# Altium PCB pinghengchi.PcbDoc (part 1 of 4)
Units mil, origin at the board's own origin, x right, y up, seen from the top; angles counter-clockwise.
Board outline 3880 x 3935 mil, 2 copper layers (Top Layer, Bottom Layer); 79 components, 147 nets, 520 pads, 52 vias.
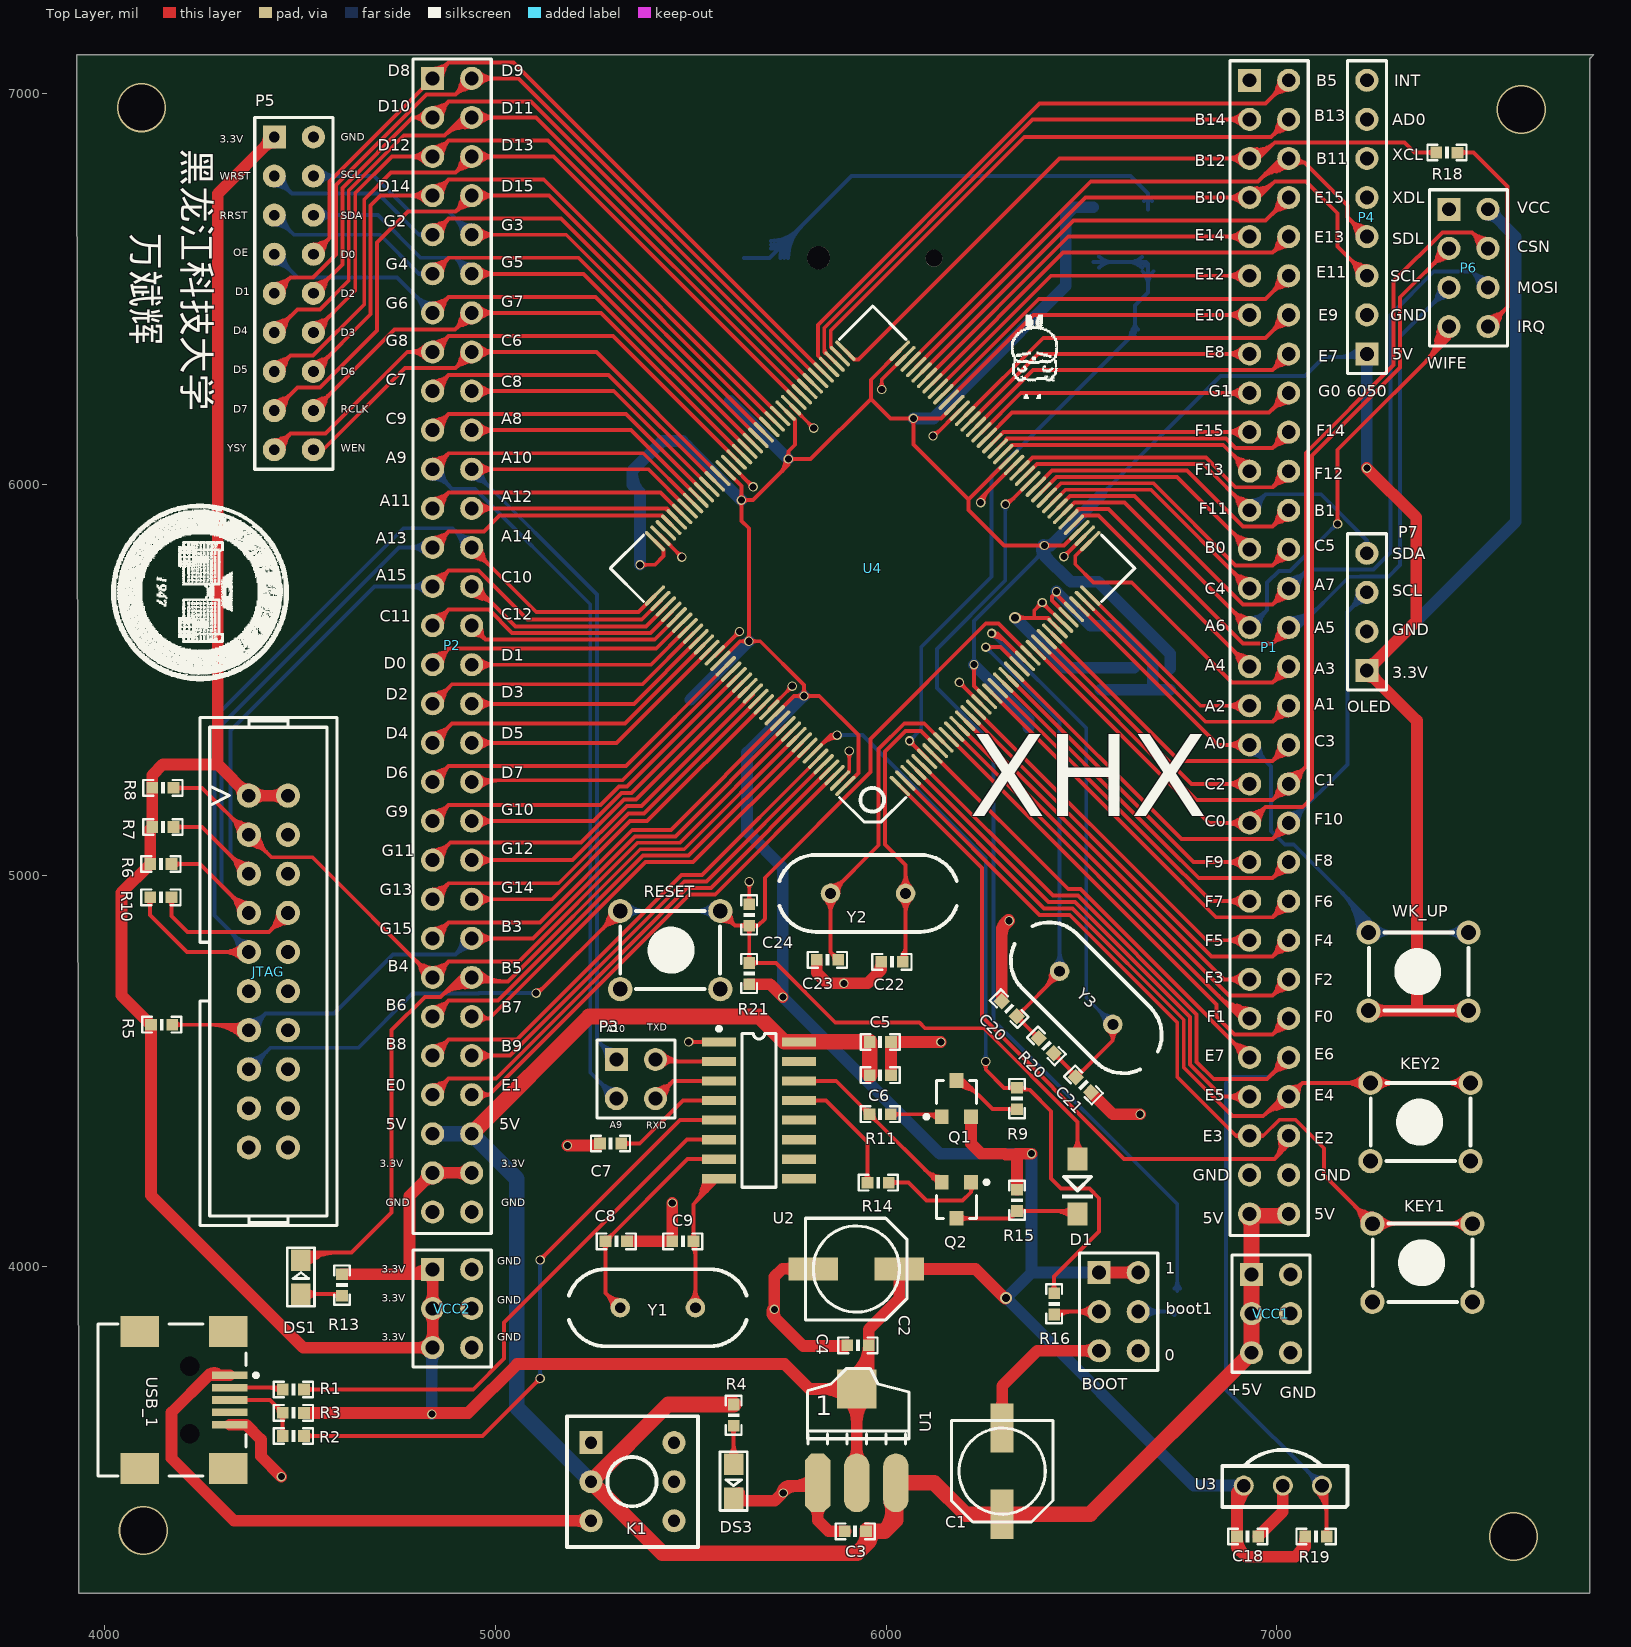
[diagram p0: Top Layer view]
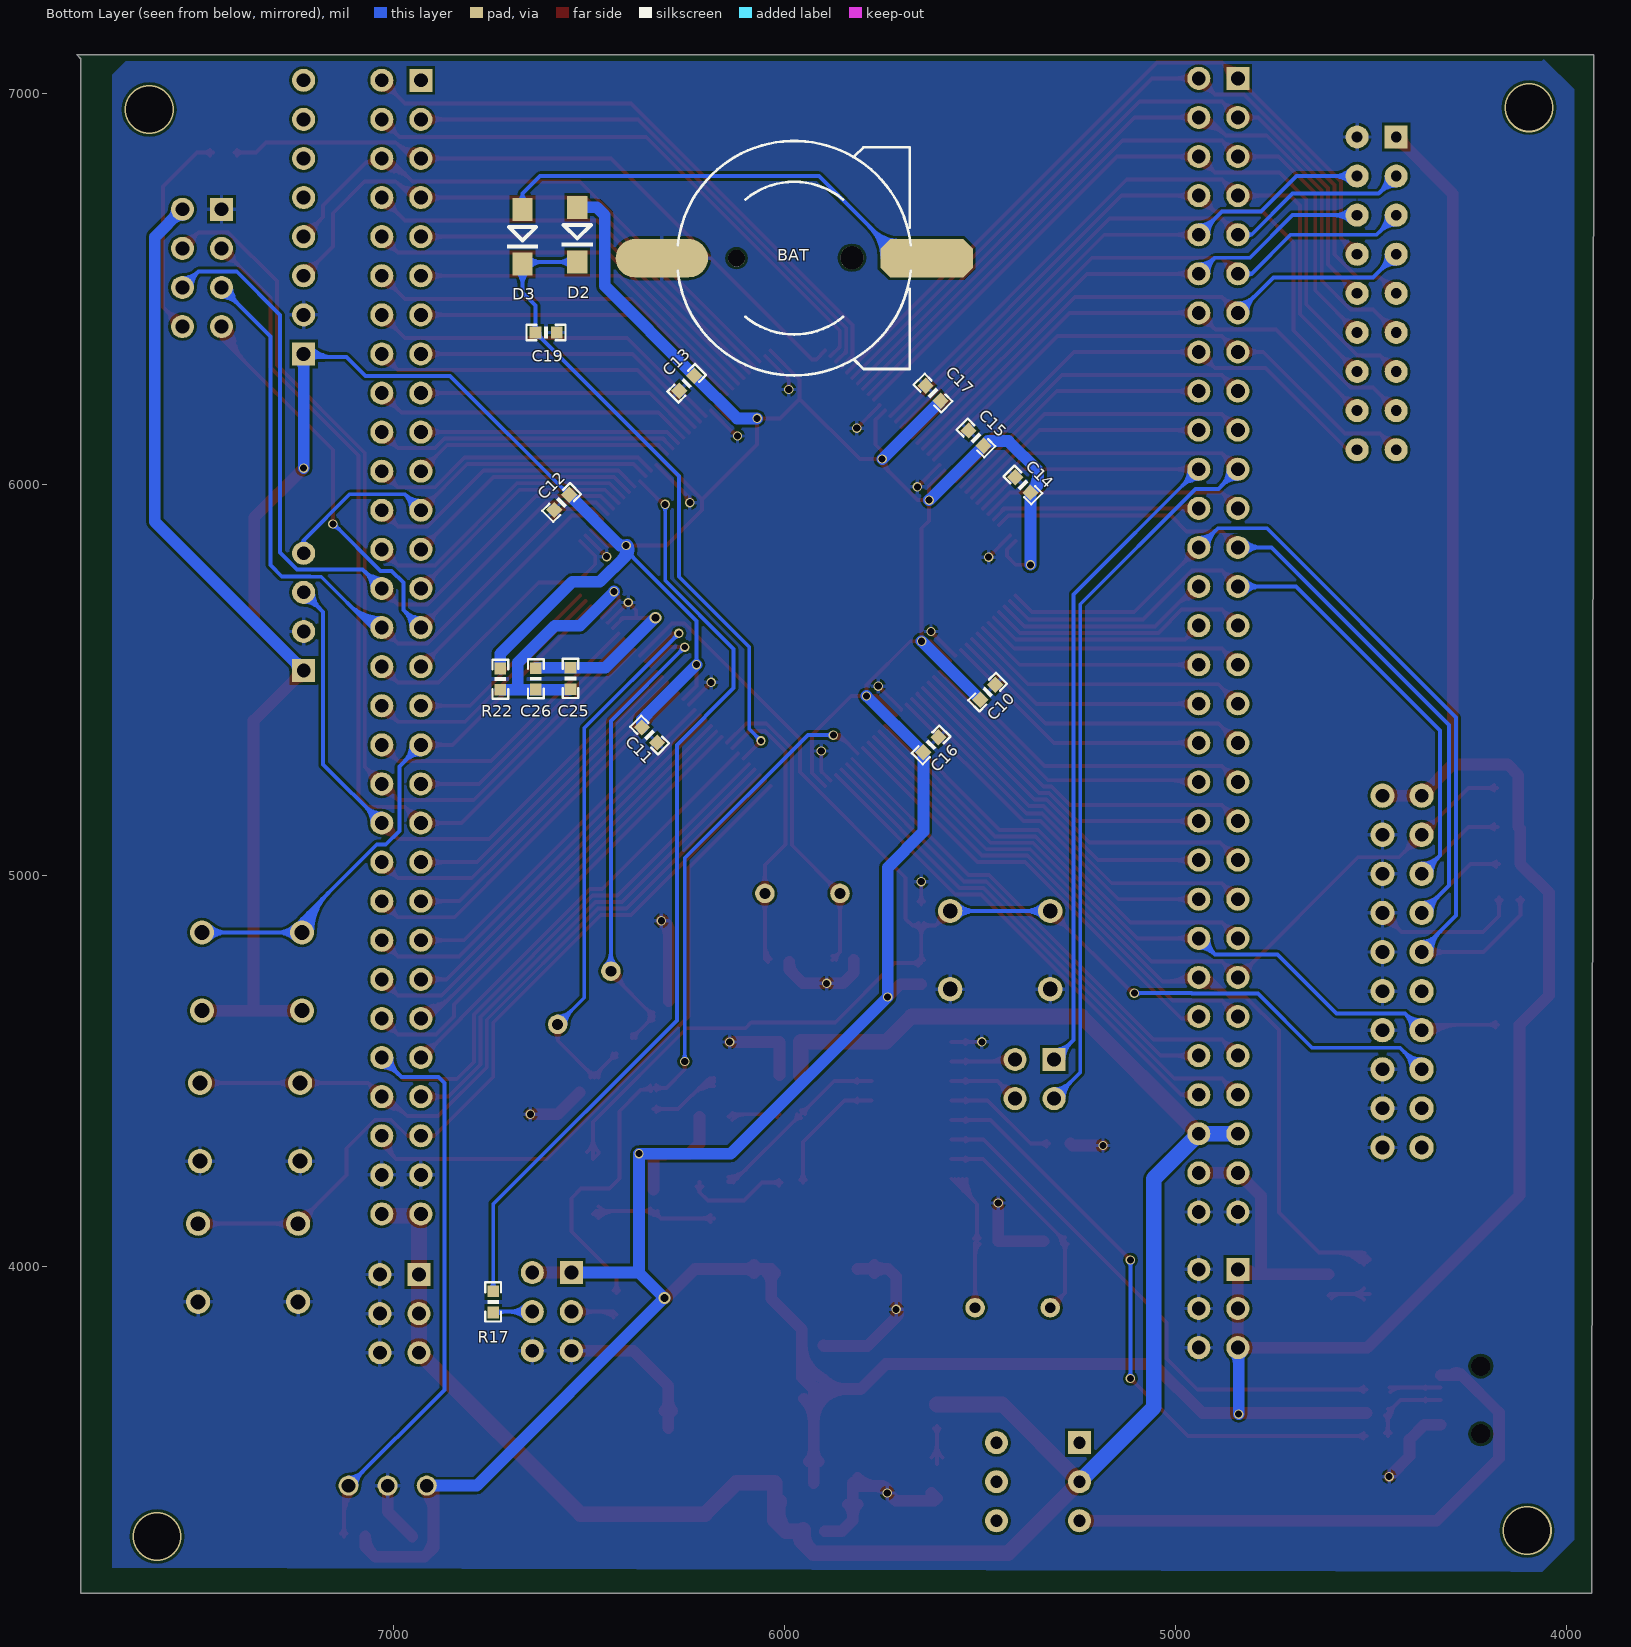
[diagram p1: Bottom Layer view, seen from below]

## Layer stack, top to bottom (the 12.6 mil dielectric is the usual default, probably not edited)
Top Layer: signal copper 1.4
Dielectric: dielectric 12.6, FR-4, Dk 4.8
Bottom Layer: signal copper 1.4

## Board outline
3930,7100 7810,7100 7800,7090 7800,3165 3935,3165 3935,3385

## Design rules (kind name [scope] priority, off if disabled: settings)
Clearance [All] p1: gap=6.5
HoleSize [All] p1: absolutevalues=TRUE maxlimit=120 minlimit=1 maxpercent=80.000 minpercent=20.000
HoleToHoleClearance [All] p1: gap=6 allowstackedmicrovias=TRUE
MinimumSolderMaskSliver [All] p1: minsoldermaskwidth=0
PolygonConnect [All] p1: connectstyle=Relief reliefconductorwidth=10 reliefentries=4 polygonreliefangle="90 Angle"
RoutingVias [All] p1: holewidth=16 width=24 viastyle="Through Hole" minholewidth=28 minwidth=50 maxholewidth=28 maxwidth=50
SilkToSilkClearance [All] p1: silktosilkclearance=1
SilkscreenOverComponentPads [All] p1: minsilkscreentomaskgap=0
SolderMaskExpansion [All] p1: expansion=2
Width [All] p1: maxlimit=80 minlimit=10 preferedwidth=10 minimp=50.000000 maximp=50.000000 favimp=50.000000
23 further rules are at their usual default settings.

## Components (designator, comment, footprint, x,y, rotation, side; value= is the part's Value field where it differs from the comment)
BAT "BATT" BATM 5975,6580 r90 bottom
BOOT "Header 3X2" HDR2X3 6545,3985 r270 top
C1 "47uf" CC6.56.5 6297,3477 r90 top
C2 "220UF" CC6.56.5 5924,3994 r180 top
C3 "100nf" 0603P 5921,3323 r0 top
C4 "100nf" 0603P 5928,3799 r0 top
C5 "100nf" 0603P 5985,4575 r0 top
C6 "10uf" 0603P 5985,4490 r0 top
C7 "104" 0603P 5295,4315 r0 top
C8 "22pf" 0603P 5310,4065 r180 top
C9 "22pf" 0603P 5480,4065 r0 top
C10 "100nf" 0603P 5480,5470 r315 bottom
C11 "100nf" 0603P 6345,5360 r45 bottom
C12 "100nf" 0603P 6570,5955 r135 bottom
C13 "100nf" 0603P 6250,6260 r135 bottom
C14 "100nf" 0603P 5390,6000 r225 bottom
C15 "100nf" 0603P 5510,6120 r225 bottom
C16 "100nf" 0603P 5625,5335 r315 bottom
C17 "100nf" 0603P 5620,6235 r225 bottom
C18 "100nf" 0603P 6925,3310 r180 top
C19 "100nf" 0603P 6610,6390 r180 bottom
C20 "20pf" 0603P 6315,4660 r315 top
C21 "20pf" 0603P 6505,4465 r135 top
C22 "10pf" 0603P 6015,4780 r0 top
C23 "10pf" 0603P 5850,4785 r0 top
C24 "100nf" 0603P 5650,4900 r270 top
C25 "10uf" 0603P 6547,5505 r270 bottom
C26 "100nf" 0603P 6636,5504 r270 bottom
D1 "1N4148" DIODE_SOP 6490,4275 r270 top
D2 "1N4148" DIODE_SOP 6530,6710 r270 bottom
D3 "1N4148" DIODE_SOP 6670,6705 r270 bottom
DS1 "LED1" SMDLED 4503,3930 r90 top
DS3 "LED1" SMDLED 5610,3495 r270 top
JTAG "JTAG" JTAG_20 4420,4755 r270 top
K1 "BUTTON" BTN8.5*8.5 5245,3550 r0 top
KEY1 "KEY_M" KEY_M 7500,3910 r180 top
KEY2 "KEY_M" KEY_M 7495,4270 r180 top
P1 "Header 30X2" HDR2X30#1 6930,7035 r270 top
P2 "Header 30X2" HDR2X30#2 4840,7040 r270 top
P3 "USART1" HDR2X2 5310,4530 r270 top
P4 "Header 8" HDR1X8 7230,6335 r90 top
P5 "OV7670" HDR2X9 4435,6890 r270 top
P6 "Header 4X2" HDR2X4 7440,6705 r270 top
P7 "Header 4" HDR1X4 7230,5525 r90 top
Q1 "S8550" SOT-23R 6180,4425 r0 top
Q2 "S8050" SOT-23R 6180,4175 r180 top
R1 "10K" 0603P 4484,3686 r180 top
R2 "10K" 0603P 4484,3567 r180 top
R3 "1.5K" 0603P 4484,3626 r180 top
R4 "2K" 0603P 5610,3620 r90 top
R5 "10K" 0603P 4147,4619 r180 top
R6 "10K" 0603P 4145,5030 r180 top
R7 "10K" 0603P 4150,5125 r180 top
R8 "10K" 0603P 4150,5225 r180 top
R9 "1K" 0603P 6335,4430 r90 top
R10 "10K" 0603P 4145,4945 r180 top
R11 "1K" 0603P 5985,4390 r180 top
R13 "600" 0603P 4608,3953 r90 top
R14 "1K" 0603P 5980,4215 r180 top
R15 "10K" 0603P 6335,4170 r270 top
R16 "100k" 0603P 6430,3905 r270 top
R17 "100k" 0603P 6745,3910 r90 bottom
R18 "1K" 0603P 7435,6850 r180 top
R19 "4.7K" 0603P 7100,3310 r180 top
R20 "1M" 0603P 6410,4565 r135 top
R21 "10K" 0603P 5650,4750 r270 top
R22 "10K" 0603P 6727,5503 r90 bottom
RESET "KEY_M" KEY_M 5320,4910 r0 top
U1 "AMS1117-3.3" AMS1117 5825,3447 r0 top
U2 "CH340G" SOP16M 5675,4400 r270 top
U3 "HS0038" HS0038 7115,3440 r180 top
U4 "STM32F103ZET6" LQFP144 6035,5230 r135 top
USB_1 "USB" USB/SM0.8-6H5 4012,3659 r180 top
VCC1 "Header 3X2" HDR2X3 6935,3980 r270 top
VCC2 "Header 3X2" HDR2X3 4840,3993 r270 top
WK_UP "KEY_M" KEY_M 7490,4655 r180 top
Y1 "12MHz" XTAL_US 5320,3895 r0 top
Y2 "32.768K" XTAL_US 6050,4955 r180 top
Y3 "8MHz" XTAL_US 6580,4620 r135 top

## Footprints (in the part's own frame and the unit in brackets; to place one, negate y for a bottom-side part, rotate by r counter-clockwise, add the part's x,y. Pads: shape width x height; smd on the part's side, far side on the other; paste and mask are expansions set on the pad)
0603P [mil]
  rect 30x30 smd: 1(-27,0) 2(27.5,-0.06)
  silkscreen extent -50,-20 50,20
AMS1117 [mil]
  oct 65x150 smd: 1(0.03,-0.06)
  oval 65x150 smd: 2(100.03,-0.06) 3(200.03,-0.06)
  rect 100x100 smd: 4(100.03,239.94)
  silkscreen extent -26,100 234,293
BATM [mm]
  round 1.1 hole 1.1 unplated: 0(0,3.748)
  round 1.5 hole 1.5 unplated: 0(0.025,-3.752)
  oct 2.5x6 smd: 1(0,-8.602)
  oval 2.5x6 smd: 2(0,8.598)
  silkscreen extent -7.62,-7.58 7.62,7.57
BTN8.5*8.5 [mm]
  rect 1.5x1.5 hole 0.8: 1(0,0)
  round 1.5 hole 0.8: 2(0,-2.54) 3(0,-5.08) 4(5.4,-5.08) 5(5.4,-2.54) 6(5.4,0)
  silkscreen extent -1.55,-6.79 6.95,1.71
CC6.56.5 [mm]
  rect 3.2x1.5 smd: 1(-2.794,0) 2(2.8,0)
  silkscreen extent -3.3,-3.3 3.3,3.3
DIODE_SOP [mm]
  rect 1.5x1.3 smd: 1(0,0) 2(3.556,0)
  silkscreen extent 1.14,-1.02 2.56,1.02
HDR1X4 [mm]
  rect 1.5x1.5 hole 0.889: 1(0,0)
  round 1.5 hole 0.889: 2(2.54,0) 3(5.08,0) 4(7.62,0)
  silkscreen extent -1.27,-1.27 8.89,1.27
HDR1X8 [mm] "Connector; Header; 8 Position"
  rect 1.5x1.5 hole 0.9: 1(0,0)
  round 1.5 hole 0.9: 2(2.54,0) 3(5.08,0) 4(7.62,0) 5(10.16,0) 6(12.7,0) 7(15.24,0) 8(17.78,0)
  silkscreen extent -1.27,-1.27 19.05,1.27
HDR2X2 [mm]
  rect 1.5x1.5 hole 0.9: 1(0,0)
  round 1.5 hole 0.9: 2(0,2.54) 3(2.54,0) 4(2.54,2.54)
  silkscreen extent -1.27,-1.27 3.81,3.81
HDR2X3 [mm]
  rect 1.5x1.5 hole 0.9: 1(0,0)
  round 1.5 hole 0.9: 2(0,2.54) 3(2.54,0) 4(2.54,2.54) 5(5.08,0) 6(5.08,2.54)
  silkscreen extent -1.27,-1.27 6.35,3.81
HDR2X4 [mm] "Connector; Header; 4x2 Position"
  rect 1.5x1.5 hole 0.9: 1(0,0)
  round 1.5 hole 0.9: 2(0,2.54) 3(2.54,0) 4(2.54,2.54) 5(5.08,0) 6(5.08,2.54) 7(7.62,0) 8(7.62,2.54)
  silkscreen extent -1.27,-1.27 8.89,3.81
HDR2X9 [mm]
  rect 1.5x1.5 hole 0.7: 1(0,0)
  round 1.5 hole 0.7: 2(0,2.54) 3(2.54,0) 4(2.54,2.54) 5(5.08,0) 6(5.08,2.54) 7(7.62,0) 8(7.62,2.54) 9(10.16,0) 10(10.16,2.54) 11(12.7,0) 12(12.7,2.54) 13(15.24,0) 14(15.24,2.54) 15(17.78,0) 16(17.78,2.54) 17(20.32,0) 18(20.32,2.54)
  silkscreen extent -1.27,-1.27 21.59,3.81
HDR2X30#1 [mm] "Connector; Header; 30x2 Position"
  rect 1.5x1.5 hole 0.9: 1(0,0)
  round 1.5 hole 0.9: 2(0,2.54) 3(2.54,0) 4(2.54,2.54) 5(5.08,0) 6(5.08,2.54) 7(7.62,0) 8(7.62,2.54) 9(10.16,0) 10(10.16,2.54) 11(12.7,0) 12(12.7,2.54) 13(15.24,0) 14(15.24,2.54) 15(17.78,0) 16(17.78,2.54) 17(20.32,0) 18(20.32,2.54) 19(22.86,0) 20(22.86,2.54) 21(25.4,0) 22(25.4,2.54) 23(27.94,0) 24(27.94,2.54) 25(30.48,0) 26(30.48,2.54) 27(33.02,0) 28(33.02,2.54) 29(35.56,0) 30(35.56,2.54) 31(38.1,0) 32(38.1,2.54) 33(40.64,0) 34(40.64,2.54) 35(43.18,0) 36(43.18,2.54) 37(45.72,0) 38(45.72,2.54) 39(48.26,0) 40(48.26,2.54) 41(50.8,0) 42(50.8,2.54) 43(53.34,0) 44(53.34,2.54) 45(55.88,0) 46(55.88,2.54) 47(58.42,0) 48(58.42,2.54) 49(60.96,0) 50(60.96,2.54) 51(63.5,0) 52(63.5,2.54) 53(66.04,0) 54(66.04,2.54) 55(68.58,0) 56(68.58,2.54) 57(71.12,0) 58(71.12,2.54) 59(73.66,0) 60(73.66,2.54)
  silkscreen extent -1.27,-1.27 75.06,3.81
HDR2X30#2 [mm] "Connector; Header; 30x2 Position"
  rect 1.5x1.5 hole 0.9: 1(0,0)
  round 1.5 hole 0.9: 2(0,2.54) 3(2.54,0) 4(2.54,2.54) 5(5.08,0) 6(5.08,2.54) 7(7.62,0) 8(7.62,2.54) 9(10.16,0) 10(10.16,2.54) 11(12.7,0) 12(12.7,2.54) 13(15.24,0) 14(15.24,2.54) 15(17.78,0) 16(17.78,2.54) 17(20.32,0) 18(20.32,2.54) 19(22.86,0) 20(22.86,2.54) 21(25.4,0) 22(25.4,2.54) 23(27.94,0) 24(27.94,2.54) 25(30.48,0) 26(30.48,2.54) 27(33.02,0) 28(33.02,2.54) 29(35.56,0) 30(35.56,2.54) 31(38.1,0) 32(38.1,2.54) 33(40.64,0) 34(40.64,2.54) 35(43.18,0) 36(43.18,2.54) 37(45.72,0) 38(45.72,2.54) 39(48.26,0) 40(48.26,2.54) 41(50.8,0) 42(50.8,2.54) 43(53.34,0) 44(53.34,2.54) 45(55.88,0) 46(55.88,2.54) 47(58.42,0) 48(58.42,2.54) 49(60.96,0) 50(60.96,2.54) 52(63.5,2.54) 53(66.04,0) 54(66.04,2.54) 55(68.58,0) 56(68.58,2.54) 57(71.12,0) 58(71.12,2.54) 59(73.66,0) 60(73.66,2.54)
  round 1.499 hole 0.9: 51(63.5,0)
  silkscreen extent -1.27,-1.27 75.06,3.81
HS0038 [mm]
  round 1.3 hole 0.889: 1(0,0) 2(2.54,0) 3(5.08,0)
  silkscreen extent -1.65,-2.32 6.48,1.4
JTAG_20 [mil]
  round 62 hole 35: 1(-450,-50) 2(-450,50) 3(-350,-50) 4(-350,50) 5(-250,-50) 6(-250,50) 7(-150,-50) 8(-150,50) 9(-50,-50) 10(-50,50) 11(50,-50) 12(50,50) 13(150,-50) 14(150,50) 15(250,-50) 16(250,50) 17(350,-50) 18(350,50) 19(450,-50) 20(450,50)
  silkscreen extent -650,-175 650,175
KEY_M [mil]
  round 62 hole 38: 1(0,0) 1(255.91,0) 2(0,-200) 2(255.91,-200)
  silkscreen extent 0,-200 255,0
LQFP144 [mil]
  oval 70x9.5 smd: 1(-0.36,0.02) 2(-0.35,-19.66) 3(-0.35,-39.35) 4(-0.35,-59.03) 5(-0.35,-78.72) 6(-0.35,-98.4) 7(-0.35,-118.09) 8(-0.35,-137.77) 9(-0.35,-157.46) 10(-0.35,-177.14) 11(-0.35,-196.83) 12(-0.36,-216.51) 13(-0.35,-236.2) 14(-0.35,-255.88) 15(-0.35,-275.57) 16(-0.35,-295.25) 17(-0.35,-314.94) 18(-0.35,-334.62) 19(-0.35,-354.31) 20(-0.35,-373.99) 21(-0.35,-393.68) 22(-0.35,-413.36) 23(-0.35,-433.05) 24(-0.35,-452.73) 25(-0.35,-472.42) 26(-0.35,-492.1) 27(-0.35,-511.79) 28(-0.36,-531.47) 29(-0.35,-551.16) 30(-0.35,-570.84) 31(-0.35,-590.53) 32(-0.35,-610.21) 33(-0.35,-629.9) 34(-0.35,-649.58) 35(-0.35,-669.27) 36(-0.35,-688.95) 73(885.47,-688.95) 74(885.47,-669.27) 75(885.47,-649.58) 76(885.47,-629.9) 77(885.47,-610.21) 78(885.47,-590.53) 79(885.47,-570.84) 80(885.47,-551.16) 81(885.47,-531.47) 82(885.47,-511.79) 83(885.47,-492.1) 84(885.47,-472.42) 85(885.47,-452.73) 86(885.47,-433.05) 87(885.47,-413.36) 88(885.47,-393.68) 89(885.47,-373.99) 90(885.47,-354.31) 91(885.47,-334.62) 92(885.47,-314.94) 93(885.47,-295.25) 94(885.47,-275.57) 95(885.47,-255.88) 96(885.47,-236.2) 97(885.47,-216.51) 98(885.47,-196.83) 99(885.47,-177.14) 100(885.47,-157.46) 101(885.47,-137.77) 102(885.47,-118.09) 103(885.47,-98.4) 104(885.47,-78.72) 105(885.47,-59.03) 106(885.47,-39.35) 107(885.47,-19.66) 108(885.47,0.02)
  oval 9.5x70 smd: 37(98.07,-787.38) 38(117.76,-787.38) 39(137.44,-787.38) 40(157.13,-787.38) 41(176.81,-787.38) 42(196.5,-787.38) 43(216.18,-787.38) 44(235.87,-787.38) 45(255.55,-787.38) 46(275.24,-787.38) 47(294.92,-787.38) 48(314.61,-787.38) 49(334.29,-787.38) 50(353.98,-787.38) 51(373.66,-787.38) 52(393.35,-787.38) 53(413.03,-787.38) 54(432.72,-787.38) 55(452.4,-787.38) 56(472.09,-787.38) 57(491.77,-787.38) 58(511.46,-787.38) 59(531.14,-787.38) 60(550.83,-787.38) 61(570.51,-787.38) 62(590.2,-787.38) 63(609.88,-787.38) 64(629.57,-787.38) 65(649.25,-787.38) 66(668.94,-787.38) 67(688.62,-787.38) 68(708.31,-787.38) 69(727.99,-787.38) 70(747.68,-787.38) 71(767.36,-787.38) 72(787.05,-787.38) 109(787.05,98.45) 110(767.36,98.45) 111(747.67,98.45) 112(727.99,98.45) 113(708.31,98.45) 114(688.62,98.45) 115(668.94,98.45) 116(649.25,98.45) 117(629.57,98.45) 118(609.88,98.45) 119(590.2,98.45) 120(570.51,98.45) 121(550.82,98.45) 122(531.14,98.45) 123(511.46,98.45) 124(491.77,98.45) 125(472.09,98.45) 126(452.4,98.45) 127(432.72,98.45) 128(413.03,98.45) 129(393.35,98.45) 130(373.66,98.45) 131(353.98,98.45) 132(334.29,98.45) 133(314.61,98.45) 134(294.92,98.45) 135(275.24,98.45) 136(255.55,98.45) 137(235.87,98.45) 138(216.18,98.45) 139(196.5,98.45) 140(176.81,98.45) 141(157.13,98.45) 142(137.44,98.45) 143(117.76,98.45) 144(98.07,98.45)
  silkscreen extent -32,-819 917,130
SMDLED [mm]
  rect 1.4x1.27 smd: 1(0.001,-0.002) 2(2.211,-0.002)
  silkscreen extent -0.8,-0.89 3.01,0.89
SOP16M [mm]
  rect 0.6x2.2 smd: 1(-4.445,-2.6) 2(-3.175,-2.6) 3(-1.905,-2.6) 4(-0.635,-2.6) 5(0.635,-2.6) 6(1.905,-2.6) 7(3.175,-2.6) 8(4.445,-2.6) 9(4.445,2.6) 10(3.175,2.6) 11(1.905,2.6) 12(0.635,2.6) 13(-0.635,2.6) 14(-1.905,2.6) 15(-3.175,2.6) 16(-4.445,2.6)
  silkscreen extent -5.42,-2.72 5,1.1
SOT-23R [mm]
  rect 0.9x0.95 smd: 1(0.95,-1.048) 2(-0.95,-1.048) 3(0,1.302)
  silkscreen extent -2.07,-1.17 1.3,1.3
USB/SM0.8-6H5 [mm]
  rect 2.3x0.5 smd: 1(-7.85,-1.6) 2(-7.85,-0.8) 3(-7.85,0) 4(-7.85,0.8) 5(-7.85,1.6)
  rect 2.5x2 smd: 6(-7.75,4.45) 7(-1.996,4.45) 8(-7.75,-4.45) 9(-1.996,-4.45)
  round 0.6 hole 1.27 unplated: MH1(-5.25,2.2) MH2(-5.25,-2.2)
  silkscreen extent -9.68,-4.95 0.7,4.95
XTAL_US [mil]
  round 50 hole 28: 1(0,0) 2(192.13,0)
  silkscreen extent -131,-98 323,98

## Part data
BOOT VCC1 VCC2: "Header,"
DS1 DS3: library part LED2, "Typical RED, GREEN, YELLOW,"
P1 P2: "Header, 30-Pin, Dual row"
P3: library part "Header 2X2", "Header,"
P4: "Header, 8-Pin"
P5: library part "Header 9X2", "Header,"
P6: "Header, 4-Pin, Dual row"
Q2: library part NPN, "805"
U2: library part C
Y1 Y2 Y3: library part XTAL, "Cr"

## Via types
v1: diameter 24, hole 18, Top Layer to Bottom Layer, 42 vias
v2: diameter 24, hole 16, Top Layer to Bottom Layer, 4 vias
v3: diameter 125.98, hole 118.11, Top Layer to Bottom Layer, 4 vias
v4: diameter 30, hole 20, Top Layer to Bottom Layer, 2 vias

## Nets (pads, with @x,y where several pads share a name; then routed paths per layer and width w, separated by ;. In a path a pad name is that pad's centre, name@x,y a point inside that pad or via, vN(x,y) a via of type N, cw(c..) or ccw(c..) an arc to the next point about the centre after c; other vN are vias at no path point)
+3.3V: BOOT.1 BOOT.2 C2.1 C4.2 C10.2 C11.2 C12.2 C13.2 C14.2 C15.2 C16.2 C17.2 C18.2 D2.1 JTAG.1 JTAG.2 P2.57 P2.58 P4.1 P5.1 P6.2 P7.1 Q1.1 R3.1 R5.2 R6.2 R7.2 R8.2 R13.2 R15.1 R19.2 R21.2 R22.2 U1.2 U1.4 U3.3 U4.17 U4.39 U4.52 U4.62 U4.72 U4.84 U4.95 U4.108 U4.121 U4.131 U4.144 VCC2.1 VCC2.3 VCC2.5 WK_UP.1 | length 28510
  Top Layer w10: v1(5370.6,5795.6) 5408.6,5795.6 5430.6,5817.6 5430.6,5834.37 U4.108@5408.86,5856.11 ; U4.121@5575.89,5549.88 5626.02,5600 v1(5648.89,5600) ; U4.95@5589.81,6037.06 5630,5996.87 v1(5630,5961.11) ; U4.131@5715.09,5410.69 5764.4,5460 v1(5790,5460) ; 5734.87,6035.77 cw(c5773.49,6025.42) v1@5753.5,6060.05 ; U4.84@5742.93,6190.17 5766.65,6166.45 5766.65,6102.65 5750,6086 v1(5750,6066.11) ; U4.144@5896.04,5229.73 5929.34,5263.03 5929.34,5359.66 5829,5460 v1(5790,5460) ; U4.72@6035.23,6343.28 5961,6269.05 5961,6220.05 ; U4.62@6174.43,6204.09 6140.34,6170 v1(6070,6170) ; v1(6225,5540) 6225,5485.39 U4.17@6257.94,5452.44 ; U4.52@6313.62,6064.9 6211,5962.28 ; U4.39@6494.57,5883.94 6455.63,5845 v1(6405,5845) 6302,5845 6211,5936 6211,5962.28 ; 5387.5,5795.6 ccw(c5387.5,5778.7) 5375.55,5790.65 cw(c5387.5,5778.7) 5387.5,5795.6 ; 5387.5,5795.6 cw(c5387.5,5812.5) 5375.55,5800.55 ccw(c5387.5,5812.5) 5387.5,5795.6 ; 5630,5944.21 ccw(c5613.1,5944.21) 5625.05,5956.16 cw(c5613.1,5944.21) 5630,5944.21 ; 5630,5944.21 cw(c5646.9,5944.21) v1@5634.95,5956.16 ; 5630,5944.21 cw(c5646.9,5944.21) v1@5634.95,5956.16 ; v1(5630,5961.11) 5630,5908 5648.89,5889.11 v1(5648.89,5600) ; v1(5630,5961.11) 5659.34,5961.11 5750,6051.77 ; 5630,5978.01 ccw(c5646.9,5978.01) v1@5634.95,5966.06 ; 5630,5978.01 cw(c5613.1,5978.01) 5625.05,5966.06 ccw(c5613.1,5978.01) 5630,5978.01 ; 5630,5978.01 ccw(c5646.9,5978.01) v1@5634.95,5966.06 ; 5631.99,5600 ccw(c5631.99,5616.9) v1@5643.94,5604.95 ; 5631.99,5600 cw(c5631.99,5583.1) 5643.94,5595.05 ccw(c5631.99,5583.1) 5631.99,5600 ; 5631.99,5600 ccw(c5631.99,5616.9) v1@5643.94,5604.95 ; v1@5634.95,5956.16 cw(c5646.9,5944.21) 5646.9,5961.11 ; v1@5634.95,5956.16 cw(c5646.9,5944.21) 5646.9,5961.11 ; v1@5634.95,5966.06 ccw(c5646.9,5978.01) 5646.9,5961.11 ; v1@5634.95,5966.06 ccw(c5646.9,5978.01) 5646.9,5961.11 ; v1@5643.94,5604.95 ccw(c5631.99,5616.9) 5648.89,5616.9 ; v1@5643.94,5604.95 ccw(c5631.99,5616.9) 5648.89,5616.9 ; v1(5648.89,5600) 5678.23,5600 5790,5488.23 v1(5790,5460) ; 5648.89,5616.9 ccw(c5665.79,5616.9) v1@5653.84,5604.95 ; 5648.89,5616.9 ccw(c5665.79,5616.9) v1@5653.84,5604.95 ; v1@5653.84,5604.95 ccw(c5665.79,5616.9) 5665.79,5600 ; v1@5653.84,5604.95 ccw(c5665.79,5616.9) 5665.79,5600 ; 5665.79,5600 ccw(c5665.79,5583.1) 5653.84,5595.05 cw(c5665.79,5583.1) 5665.79,5600 ; 5750,6051.77 ccw(c5738.8,6051.77) 5745.69,6060.59 cw(c5738.8,6051.77) 5750,6051.77 ; 5750,6051.77 cw(c5761.2,6051.77) 5754.31,6060.59 ccw(c5761.2,6051.77) 5750,6051.77 ; 5750,6051.77 v1(5750,6066.11) ; v1(5750,6066.11) 5807.06,6066.11 5961,6220.05 ; 5750,6083.01 ccw(c5766.9,6083.01) v1@5754.95,6071.06 ; 5750,6083.01 cw(c5733.1,6083.01) 5745.05,6071.06 ccw(c5733.1,6083.01) 5750,6083.01 ; 5750,6083.01 ccw(c5766.9,6083.01) v1@5754.95,6071.06 ; v1@5754.95,6071.06 ccw(c5766.9,6083.01) 5766.9,6066.11 ; v1@5754.95,6071.06 ccw(c5766.9,6083.01) 5766.9,6066.11 ; 5766.9,6066.11 ccw(c5766.9,6049.21) 5754.95,6061.16 cw(c5766.9,6049.21) 5766.9,6066.11 ; 5773.1,5460 ccw(c5773.1,5476.9) v1@5785.05,5464.95 ; 5773.1,5460 cw(c5773.1,5443.1) 5785.05,5455.05 ccw(c5773.1,5443.1) 5773.1,5460 ; 5773.1,5460 ccw(c5773.1,5476.9) v1@5785.05,5464.95 ; v1@5785.05,5464.95 ccw(c5773.1,5476.9) 5790,5476.9 ; v1@5785.05,5464.95 ccw(c5773.1,5476.9) 5790,5476.9 ; 5790,5476.9 ccw(c5806.9,5476.9) v1@5794.95,5464.95 ; 5790,5476.9 ccw(c5806.9,5476.9) v1@5794.95,5464.95 ; v1@5794.95,5464.95 ccw(c5806.9,5476.9) 5806.9,5460 ; v1@5794.95,5464.95 ccw(c5806.9,5476.9) 5806.9,5460 ; 5806.9,5460 ccw(c5806.9,5443.1) 5794.95,5455.05 cw(c5806.9,5443.1) 5806.9,5460 ; 5961,6220.05 6011.05,6170 v1(6070,6170) ; 6053.1,6170 ccw(c6053.1,6186.9) 6065.05,6174.95 cw(c6053.1,6186.9) 6053.1,6170 ; 6053.1,6170 cw(c6053.1,6153.1) v1@6065.05,6165.05 ; 6053.1,6170 cw(c6053.1,6153.1) v1@6065.05,6165.05 ; v1@6065.05,6165.05 cw(c6053.1,6153.1) 6070,6153.1 ; v1@6065.05,6165.05 cw(c6053.1,6153.1) 6070,6153.1 ; 6070,6153.1 cw(c6086.9,6153.1) v1@6074.95,6165.05 ; 6070,6153.1 cw(c6086.9,6153.1) v1@6074.95,6165.05 ; v1(6070,6170) 6070,6103.28 6211,5962.28 ; v1@6074.95,6165.05 cw(c6086.9,6153.1) 6086.9,6170 ; v1@6074.95,6165.05 cw(c6086.9,6153.1) 6086.9,6170 ; 6086.9,6170 cw(c6086.9,6186.9) 6074.95,6174.95 ccw(c6086.9,6186.9) 6086.9,6170 ; 6225,5523.1 ccw(c6208.1,5523.1) 6220.05,5535.05 cw(c6208.1,5523.1) 6225,5523.1 ; 6225,5523.1 cw(c6241.9,5523.1) 6229.95,5535.05 ccw(c6241.9,5523.1) 6225,5523.1 ; 6388.1,5845 ccw(c6388.1,5861.9) 6400.05,5849.95 cw(c6388.1,5861.9) 6388.1,5845 ; 6388.1,5845 cw(c6388.1,5828.1) 6400.05,5840.05 ccw(c6388.1,5828.1) 6388.1,5845 ; 6421.9,5845 ccw(c6421.9,5828.1) 6409.95,5840.05 cw(c6421.9,5828.1) 6421.9,5845 ; 6421.9,5845 cw(c6421.9,5861.9) 6409.95,5849.95 ccw(c6421.9,5861.9) 6421.9,5845 ; 5727.91,6029.67 ccw(c5691.47,6066.11) 5743,6066.11 cw(c5691.47,6066.11) 5727.91,6029.67 ; 5744.98,6046.74 ccw(c5725.61,6066.11) 5753,6066.11 cw(c5725.61,6066.11) 5744.98,6046.74 ; U4.84@5764.49,6168.96 cw(c5759.29,6163.76) 5766.65,6163.76 ccw(c5759.29,6163.76) U4.84@5764.49,6168.96
  Top Layer w30: P5.1@4435,6890 4290,6745 4290,5285 ; JTAG.2@4470,5205 JTAG.1@4370,5205 4290,5285 ; R3.1@4511,3626 4931,3626 5056,3751 5741,3751 5805.06,3686.94 U1.4@5925.03,3686.94 ; R13.2@4608.06,3980.5 4781,3980.5 ; 4806.46,3987.15 cw(c4815.79,3973.42) VCC2.1@4828.7,3983.86 ; P2.58@4940,4240 P2.57@4840,4240 4781,4181 4781,3980.5 ; R21.2@5649.94,4722.5 5703.5,4722.5 v1(5736,4690) ; U1.2@5925.03,3446.94 U1.4@5925.03,3686.94 ; Q1.1@6217.4,4383.74 6217.4,4314.6 6243,4289 6304,4289 ; 6306,4287 6335,4287 ; v4(6307,3920) 6305,3918 6229,3994 C2.1@6034,3994 6034,3918 5955.5,3839.5 C4.2@5955.5,3798.94 ; R15.1@6335,4197 6335,4287 ; v1(6372,4289) 6333,4289 6335,4287 ; BOOT.1@6545,3985 BOOT.2@6645,3985 ; 6903.36,3399.38 ccw(c6868.56,3419.47) U3.3@6905.31,3435.72 ; U3.3@6915,3440 6897.5,3422.5 C18.2@6897.5,3310.06 ; v1(7230,6043) 7356,5917 7356,5651 P7.1@7230,5525 7358,5397 7358,4655 ; WK_UP.1@7234.09,4655 7358,4655 ; WK_UP.1@7490,4655 7358,4655 ; 4290,5285 4150,5285 4122.5,5257.5 R8.2@4122.5,5225.06 R7.2@4122.5,5125.06 4117.5,5120.06 R6.2@4117.5,5030.06 4044,4956.56 4044,4694.56 R5.2@4119.5,4619.06 4119.5,4182.5 4509,3793 VCC2.5@4840,3793 VCC2.3@4840,3893 VCC2.1@4840,3993 4827.5,3980.5 4781,3980.5 ; 4342.69,5232.31 ccw(c4370,5259.63) 4370,5221 cw(c4370,5259.63) 4342.69,5232.31 ; 4342.69,5232.31 cw(c4315.37,5205) 4354,5205 ccw(c4315.37,5205) 4342.69,5232.31 ; 4408.63,5205 ccw(c4408.63,5166.37) 4381.31,5193.69 cw(c4408.63,5166.37) 4408.63,5205 ; 4408.63,5205 cw(c4408.63,5243.63) 4381.31,5216.31 ccw(c4408.63,5243.63) 4408.63,5205 ; P5.1@4410.2,6865.2 ccw(c4385.4,6890) 4420.47,6890 cw(c4385.4,6890) P5.1@4410.2,6865.2 ; P5.1@4410.2,6865.2 cw(c4435,6840.4) 4435,6875.47 ccw(c4435,6840.4) P5.1@4410.2,6865.2 ; 4431.37,5205 ccw(c4431.37,5243.63) 4458.69,5216.31 cw(c4431.37,5243.63) 4431.37,5205 ; 4431.37,5205 cw(c4431.37,5166.37) 4458.69,5193.69 ccw(c4431.37,5166.37) 4431.37,5205 ; 4781,3980.5 ccw(c4781,4043.88) 4829,4002.49 cw(c4781,4043.88) 4781,3980.5 ; 4804.93,3793 ccw(c4804.93,3828.07) VCC2.5@4829.73,3803.27 ; 4804.93,3793 cw(c4804.93,3757.93) 4829.73,3782.73 ccw(c4804.93,3757.93) 4804.93,3793 ; 4804.93,3793 ccw(c4804.93,3828.07) VCC2.5@4829.73,3803.27 ; 4815.2,4215.2 ccw(c4790.4,4240) 4825.47,4240 cw(c4790.4,4240) 4815.2,4215.2 ; 4815.2,4215.2 cw(c4840,4190.4) 4840,4225.47 ccw(c4840,4190.4) 4815.2,4215.2 ; VCC2.5@4829.73,3803.27 ccw(c4804.93,3828.07) 4840,3828.07 ; VCC2.5@4829.73,3803.27 ccw(c4804.93,3828.07) 4840,3828.07 ; 4840,3828.07 ccw(c4875.07,3828.07) 4850.27,3803.27 cw(c4875.07,3828.07) 4840,3828.07 ; 4840,3857.93 ccw(c4804.93,3857.93) 4829.73,3882.73 cw(c4804.93,3857.93) 4840,3857.93 ; 4840,3857.93 cw(c4875.07,3857.93) 4850.27,3882.73 ccw(c4875.07,3857.93) 4840,3857.93 ; 4840,3928.07 ccw(c4875.07,3928.07) 4850.27,3903.27 cw(c4875.07,3928.07) 4840,3928.07 ; 4840,3928.07 cw(c4804.93,3928.07) 4829.73,3903.27 ccw(c4804.93,3928.07) 4840,3928.07 ; 4840,3957.93 ccw(c4804.93,3957.93) 4829.73,3982.73 cw(c4804.93,3957.93) 4840,3957.93 ; 4840,3957.93 cw(c4875.07,3957.93) 4850.27,3982.73 ccw(c4875.07,3957.93) 4840,3957.93 ; 4875.07,4240 ccw(c4875.07,4204.93) 4850.27,4229.73 cw(c4875.07,4204.93) 4875.07,4240 ; 4875.07,4240 cw(c4875.07,4275.07) 4850.27,4250.27 ccw(c4875.07,4275.07) 4875.07,4240 ; 4904.93,4240 ccw(c4904.93,4275.07) 4929.73,4250.27 cw(c4904.93,4275.07) 4904.93,4240 ; 4904.93,4240 cw(c4904.93,4204.93) 4929.73,4229.73 ccw(c4904.93,4204.93) 4904.93,4240 ; 5840.53,3686.94 ccw(c5840.53,3771.44) 5900.28,3711.69 cw(c5840.53,3771.44) 5840.53,3686.94 ; 5840.53,3686.94 cw(c5840.53,3602.44) U1.4@5900.28,3662.19 ; 5840.53,3686.94 cw(c5840.53,3602.44) U1.4@5900.28,3662.19 ; U1.4@5900.28,3662.19 cw(c5840.53,3602.44) 5925.03,3602.44 ; U1.4@5900.28,3662.19 cw(c5840.53,3602.44) 5925.03,3602.44 ; 5925.03,3531.68 ccw(c5967.28,3531.68) 5937.41,3501.81 cw(c5967.28,3531.68) 5925.03,3531.68 ; 5925.03,3531.68 cw(c5882.78,3531.68) 5912.66,3501.81 ccw(c5882.78,3531.68) 5925.03,3531.68 ; 5925.03,3602.44 cw(c6009.53,3602.44) 5949.78,3662.19 ccw(c6009.53,3602.44) 5925.03,3602.44 ; U1.4@5925.03,3686.94 5955.5,3717.41 C4.2@5955.5,3798.94 ; C4.2@5955.5,3798.94 cw(c5861.97,3798.93) 5907.86,3717.44 ccw(c5861.97,3798.93) C4.2@5955.5,3798.94 ; 6034,3958.93 ccw(c5998.93,3958.93) 6023.73,3983.73 cw(c5998.93,3958.93) 6034,3958.93 ; 6034,3958.93 cw(c6069.07,3958.93) 6044.27,3983.73 ccw(c6069.07,3958.93) 6034,3958.93 ; 6102.54,3994 ccw(c6102.54,3958.93) 6077.74,3983.73 cw(c6102.54,3958.93) 6102.54,3994 ; 6102.54,3994 cw(c6102.54,4029.07) 6077.74,4004.27 ccw(c6102.54,4029.07) 6102.54,3994 ; 6580.07,3985 ccw(c6580.07,3949.93) 6555.27,3974.73 cw(c6580.07,3949.93) 6580.07,3985 ; 6580.07,3985 cw(c6580.07,4020.07) 6555.27,3995.27 ccw(c6580.07,4020.07) 6580.07,3985 ; 6609.93,3985 ccw(c6609.93,4020.07) 6634.73,3995.27 cw(c6609.93,4020.07) 6609.93,3985 ; 6609.93,3985 cw(c6609.93,3949.93) 6634.73,3974.73 ccw(c6609.93,3949.93) 6609.93,3985 ; C18.2@6897.5,3310.06 ccw(c6966.46,3310.06) 6917.7,3261.3 cw(c6966.46,3310.06) C18.2@6897.5,3310.06 ; C18.2@6897.5,3310.06 6897.5,3281.5 6921,3258 7047,3258 7072.5,3283.5 R19.2@7072.5,3310.06 ; R19.2@7072.5,3310.06 cw(c7008.37,3310.06) 7053.72,3264.72 ccw(c7008.37,3310.06) R19.2@7072.5,3310.06 ; P7.1@7244.53,5525 cw(c7279.6,5525) P7.1@7254.8,5549.8 ; P7.1@7244.53,5525 ccw(c7279.6,5525) P7.1@7254.8,5500.2 ; P7.1@7244.53,5525 cw(c7279.6,5525) P7.1@7254.8,5549.8 ; P7.1@7244.53,5525 ccw(c7279.6,5525) P7.1@7254.8,5500.2 ; P7.1@7254.8,5500.2 ccw(c7230,5475.4) 7230,5510.47 cw(c7230,5475.4) P7.1@7254.8,5500.2 ; P7.1@7254.8,5549.8 cw(c7230,5574.6) 7230,5539.53 ccw(c7230,5574.6) P7.1@7254.8,5549.8 ; 7272.72,4655 ccw(c7272.72,4616.37) 7245.41,4643.69 cw(c7272.72,4616.37) 7272.72,4655 ; 7272.72,4655 cw(c7272.72,4693.63) 7245.41,4666.31 ccw(c7272.72,4693.63) 7272.72,4655 ; 7451.37,4655 ccw(c7451.37,4693.63) 7478.69,4666.31 cw(c7451.37,4693.63) 7451.37,4655 ; 7451.37,4655 cw(c7451.37,4616.37) 7478.69,4643.69 ccw(c7451.37,4616.37) 7451.37,4655 ; U1.4@5922.58,3691.29 ccw(c5890.87,3747.61) 5955.5,3747.61 cw(c5890.87,3747.61) U1.4@5922.58,3691.29 ; 6897.5,3372.18 cw(c6982.82,3372.18) 6922.49,3432.51 ccw(c6982.82,3372.18) 6897.5,3372.18
  Bottom Layer w10: v1(6225,5540) 6225,5651.67 6405,5831.67 ; C12.2@6550.51,5974.4 6855.11,6279 7072,6279 7120,6327 7222,6327 P4.1@7230,6335 ; 6225,5556.9 ccw(c6241.9,5556.9) 6229.95,5544.95 cw(c6241.9,5556.9) 6225,5556.9 ; 6225,5556.9 cw(c6208.1,5556.9) 6220.05,5544.95 ccw(c6208.1,5556.9) 6225,5556.9 ; 6567.58,5991.47 ccw(c6584.65,5974.4) 6560.51,5974.4 cw(c6584.65,5974.4) 6567.58,5991.47 ; 6567.58,5991.47 cw(c6550.51,6008.54) 6550.51,5984.4 ccw(c6550.51,6008.54) 6567.58,5991.47 ; 6383.62,5810.29 ccw(c6348.91,5845) 6398,5845 cw(c6348.91,5845) 6383.62,5810.29 ; 6400.69,5827.36 ccw(c6383.05,5845) 6408,5845 cw(c6383.05,5845) 6400.69,5827.36 ; 7151.47,6327 ccw(c7151.47,6413.53) 7212.66,6352.34 cw(c7151.47,6413.53) 7151.47,6327 ; 7175.61,6327 ccw(c7175.61,6389.39) 7219.73,6345.27 cw(c7175.61,6389.39) 7175.61,6327 ; 7190.1,6327 cw(c7190.1,6295.1) 7212.66,6317.66 ccw(c7190.1,6295.1) 7190.1,6327 ; 7199.76,6327 ccw(c7199.76,6365.24) 7226.8,6338.2 cw(c7199.76,6365.24) 7199.76,6327
  Bottom Layer w30: v1(4838,3623) 4838,3791 VCC2.5@4840,3793 ; v1(5370.6,5795.6) C14.2@5370.6,5980.51 ; C10.2@5499.49,5450.6 v1(5648.89,5600) v1@5650,5600 ; C17.2@5600.6,6215.51 v1(5750,6066.11) ; v1(5630,5961.11) C15.2@5490.6,6100.51 ; v1(5790,5460) 5645.6,5315.6 C16.2@5644.49,5315.6 5644.49,5112.51 5736,5021 v1(5736,4690) 6137,4289 v1(6372,4289) 6372,3985 ; v1(6070,6170) 6121.11,6170 C13.2@6230.51,6279.4 6460,6508.89 6460,6690 6480,6710 D2.1@6530,6710 ; v1(6225,5540) 6364.4,5400.6 C11.2@6364.4,5379.49 ; BOOT.1@6545,3985 6372,3985 ; C12.2@6550.51,5974.4 6421.11,5845 v1(6405,5845) 6405,5831.67 6405,5819.16 ; R22.2@6726.94,5530.5 6726.94,5568.06 6543,5752 6472.16,5752 6405,5819.16 ; U3.3@6915,3440 6787,3440 v4(6307,3920) 6372,3985 ; P7.1@7230,5525 7611,5906 7611,6634 P6.2@7540,6705 ; v1(7230,6043) P4.1@7230,6335 ; C14.2@5370.6,5980.51 cw(c5417.92,6027.83) 5351,6027.83 ccw(c5417.92,6027.83) C14.2@5370.6,5980.51 ; C14.2@5370.6,5980.51 5351,6000.11 5351,6036 5427,6112 5479.11,6112 C15.2@5490.6,6100.51 ; C15.2@5490.6,6100.51 ccw(c5462.86,6072.77) 5462.86,6112 cw(c5462.86,6072.77) C15.2@5490.6,6100.51 ; C11.2@6364.4,5379.49 ccw(c6313.44,5379.49) 6349.47,5415.53 cw(c6313.44,5379.49) C11.2@6364.4,5379.49 ; 6405,5819.16 cw(c6420.25,5834.41) 6402.54,5846.71 ccw(c6420.25,5834.41) 6405,5819.16 ; 6509.93,3985 ccw(c6509.93,4020.07) 6534.73,3995.27 cw(c6509.93,4020.07) 6509.93,3985 ; 6509.93,3985 cw(c6509.93,3949.93) 6534.73,3974.73 ccw(c6509.93,3949.93) 6509.93,3985 ; 7230,6299.93 ccw(c7194.93,6299.93) 7219.73,6324.73 cw(c7194.93,6299.93) 7230,6299.93 ; 7230,6299.93 cw(c7265.07,6299.93) 7240.27,6324.73 ccw(c7265.07,6299.93) 7230,6299.93 ; P7.1@7254.8,5549.8 ccw(c7279.6,5525) 7244.53,5525 cw(c7279.6,5525) P7.1@7254.8,5549.8 ; P7.1@7254.8,5549.8 cw(c7230,5574.6) 7230,5539.53 ccw(c7230,5574.6) P7.1@7254.8,5549.8 ; 7564.8,6680.2 ccw(c7540,6655.4) 7540,6690.47 cw(c7540,6655.4) 7564.8,6680.2 ; 7564.8,6680.2 cw(c7589.6,6705) 7554.53,6705 ccw(c7589.6,6705) 7564.8,6680.2 ; VCC2.5@4829.73,3782.73 cw(c4809.76,3762.76) 4838,3762.76 ccw(c4809.76,3762.76) VCC2.5@4829.73,3782.73 ; 4838,3753.1 cw(c4879.9,3753.1) 4850.27,3782.73 ccw(c4879.9,3753.1) 4838,3753.1 ; v1@6402,5845 ccw(c6457.15,5845) 6418.15,5806 cw(c6457.15,5845) v1@6402,5845 ; v1@6405,5842 ccw(c6405,5873.65) 6427.38,5851.27 cw(c6405,5873.65) v1@6405,5842
+5V: C1.1 C3.2 C5.1 C6.1 K1.2 P1.59 P1.60 P2.55 P2.56 R4.2 U1.3 U2.16 VCC1.1 VCC1.3 VCC1.5 | length 5906.6
  Top Layer w40: P2.56@4940,4340 5240,4640 5675,4640 5740,4575 U2.16@5777.36,4575 C5.1@5958,4575 C6.1@5958,4490 ; R4.2@5610.06,3647.5 5442.5,3647.5 K1.2@5245,3450 5428,3267 5926,3267 5951.5,3292.5 ; 5933.39,3274.39 ccw(c5884.85,3322.94) C3.2@5953.5,3322.94 ; 5938.51,3279.51 ccw(c5895.09,3322.94) C3.2@5956.5,3322.94 ; C3.2@5952.17,3326.33 cw(c5934.24,3309.76) 5951.5,3292.5 ; C3.2@5955.83,3325.44 cw(c5932.21,3311.79) 5951.5,3292.5 ; P1.60@7025,4130 6935,4130 VCC1.1@6935,3980 VCC1.3@6935,3880 VCC1.5@6935,3780 6522,3367 C1.1@6297,3367 6203,3367 6123.06,3446.94 U1.3@6025.03,3446.94 6025.03,3352.03 5995.94,3322.94 ; 5951.5,3292.5 5951.5,3322.94 5995.94,3322.94 ; 5995.94,3322.94 ccw(c5943.63,3375.25) 6013.27,3400.22 cw(c5943.63,3375.25) 5995.94,3322.94 ; P1.59@6923.26,4128.26 cw(c6894.93,4099.93) 6935,4099.93 ccw(c6894.93,4099.93) P1.59@6923.26,4128.26 ; P1.59@6936.74,4141.74 ccw(c6965.07,4170.07) 6965.07,4130 cw(c6965.07,4170.07) P1.59@6936.74,4141.74 ; 6994.93,4130 ccw(c6994.93,4170.07) 7023.26,4141.74 cw(c6994.93,4170.07) 6994.93,4130
  Bottom Layer w40: P2.55@4840,4340 P2.56@4940,4340 5055,4225 5055,3640 K1.2@5245,3450
AD0: P4.7
BOOT0: R9.2 R16.1 U4.138 | length 2553.2
  Top Layer w10: U4.138@5812.52,5313.25 5859.27,5360 ; 5844.66,5344.87 ccw(c5834.31,5383.49) v1@5868.94,5363.5 ; v1(5875,5360) 5859.27,5360 ; v1(6255,4525) 6255,4504 6301.5,4457.5 R9.2@6335.06,4457.5 6367.8,4451.77 6422,4397.56 6422,4226 6448,4200 6520,4200 6545,4175 6545,4090 6430,3975 R16.1@6430,3932 R16.1@6427,3935 ; 5859.27,5360 ccw(c5859.27,5374.16) 5869.8,5364.68 cw(c5859.27,5374.16) 5859.27,5360 ; 5859.27,5360 cw(c5859.27,5345.84) 5869.8,5355.32 ccw(c5859.27,5345.84) 5859.27,5360 ; 6255,4508.1 ccw(c6238.1,4508.1) 6250.05,4520.05 cw(c6238.1,4508.1) 6255,4508.1 ; 6255,4508.1 cw(c6271.9,4508.1) 6259.95,4520.05 ccw(c6271.9,4508.1) 6255,4508.1 ; 6310.92,4457.5 ccw(c6310.92,4481.64) 6327.99,4464.57 cw(c6310.92,4481.64) 6310.92,4457.5 ; 6310.92,4457.5 cw(c6310.92,4433.36) 6327.99,4450.43 ccw(c6310.92,4433.36) 6310.92,4457.5 ; 6358.84,4453.33 ccw(c6354.68,4429.55) 6340.81,4449.31 cw(c6354.68,4429.55) 6358.84,4453.33 ; 6358.84,4453.33 cw(c6363.01,4477.11) 6343.25,4463.24 ccw(c6363.01,4477.11) 6358.84,4453.33 ; 6430,3956.14 ccw(c6454.14,3956.14) 6437.07,3939.07 cw(c6454.14,3956.14) 6430,3956.14 ; 6430,3956.14 cw(c6405.86,3956.14) 6422.93,3939.07 ccw(c6405.86,3956.14) 6430,3956.14 ; U4.138@5836.2,5336.93 cw(c5875,5298.13) 5875,5353 ccw(c5875,5298.13) U4.138@5836.2,5336.93 ; 5853.28,5354 cw(c5875,5332.28) 5875,5363 ccw(c5875,5332.28) 5853.28,5354
  Bottom Layer w10: v1(5875,5360) 5940,5360 6255,5045 v1(6255,4525) ; 5891.9,5360 ccw(c5891.9,5343.1) 5879.95,5355.05 cw(c5891.9,5343.1) 5891.9,5360 ; 5891.9,5360 cw(c5891.9,5376.9) 5879.95,5364.95 ccw(c5891.9,5376.9) 5891.9,5360 ; 6255,4541.9 ccw(c6271.9,4541.9) 6259.95,4529.95 cw(c6271.9,4541.9) 6255,4541.9 ; 6255,4541.9 cw(c6238.1,4541.9) 6250.05,4529.95 ccw(c6238.1,4541.9) 6255,4541.9
BOOT1: R17.2 U4.48 | length 2603.3
  Top Layer w10: v1(6305,5950) 6310.08,5950 U4.48@6369.3,6009.22 ; v1@6305,5957 ccw(c6305,5986.16) 6325.62,5965.54 cw(c6305,5986.16) v1@6305,5957
  Bottom Layer w10: v1(6305,5950) 6305,5755 6130,5580 6130,5480 6275,5335 6275,4630 6744.94,4160.06 R17.2@6744.94,3937.5 ; 6305,5933.1 ccw(c6288.1,5933.1) 6300.05,5945.05 cw(c6288.1,5933.1) 6305,5933.1 ; 6305,5933.1 cw(c6321.9,5933.1) 6309.95,5945.05 ccw(c6321.9,5933.1) 6305,5933.1 ; 6744.94,3961.64 ccw(c6769.08,3961.64) 6752.01,3944.57 cw(c6769.08,3961.64) 6744.94,3961.64 ; 6744.94,3961.64 cw(c6720.79,3961.64) 6737.86,3944.57 ccw(c6720.79,3961.64) 6744.94,3961.64
"CH340 D+": R2.1 U2.5 | length 1913.7
  Top Layer w10: R2.1@4511,3567 4968,3567 v1(5115,3714) ; v1(5115,4017) 5473,4375 U2.5@5572.64,4375 ; 4535.14,3567 ccw(c4535.14,3542.86) 4518.07,3559.93 cw(c4535.14,3542.86) 4535.14,3567 ; 4535.14,3567 cw(c4535.14,3591.14) 4518.07,3574.07 ccw(c4535.14,3591.14) 4535.14,3567 ; 5103.05,3702.05 ccw(c5091.1,3714) 5108,3714 cw(c5091.1,3714) 5103.05,3702.05 ; 5103.05,3702.05 cw(c5115,3690.1) 5115,3707 ccw(c5115,3690.1) 5103.05,3702.05 ; 5126.95,4028.95 ccw(c5138.9,4017) 5122,4017 cw(c5138.9,4017) 5126.95,4028.95 ; 5126.95,4028.95 cw(c5115,4040.9) 5115,4024 ccw(c5115,4040.9) 5126.95,4028.95 ; 5524.7,4375 ccw(c5524.7,4391.44) 5536.33,4379.82 cw(c5524.7,4391.44) 5524.7,4375 ; 5524.7,4375 cw(c5524.7,4358.56) 5536.33,4370.18 ccw(c5524.7,4358.56) 5524.7,4375
  Bottom Layer w10: v1(5115,3714) v1(5115,4017) ; 5115,3730.9 ccw(c5131.9,3730.9) 5119.95,3718.95 cw(c5131.9,3730.9) 5115,3730.9 ; 5115,3730.9 cw(c5098.1,3730.9) 5110.05,3718.95 ccw(c5098.1,3730.9) 5115,3730.9 ; 5115,4000.1 ccw(c5098.1,4000.1) 5110.05,4012.05 cw(c5098.1,4000.1) 5115,4000.1 ; 5115,4000.1 cw(c5131.9,4000.1) 5119.95,4012.05 ccw(c5131.9,4000.1) 5115,4000.1
"CH340 D-": R1.1 U2.6 | length 1507.7
  Top Layer w10: R1.1@4511,3686 4944,3686 5023,3765 5023,3857 5491,4325 U2.6@5572.64,4325 ; 4535.14,3686 ccw(c4535.14,3661.86) 4518.07,3678.93 cw(c4535.14,3661.86) 4535.14,3686 ; 4535.14,3686 cw(c4535.14,3710.14) 4518.07,3693.07 ccw(c4535.14,3710.14) 4535.14,3686 ; 5524.7,4325 ccw(c5524.7,4341.44) 5536.33,4329.82 cw(c5524.7,4341.44) 5524.7,4325 ; 5524.7,4325 cw(c5524.7,4308.56) 5536.33,4320.18 ccw(c5524.7,4308.56) 5524.7,4325
DTR: R14.2 U2.13 | length 450.2
  Top Layer w10: U2.13@5777.36,4425 5846,4425 5952.5,4318.5 R14.2@5952.5,4215.06 ; 5825.3,4425 ccw(c5825.3,4408.56) 5813.67,4420.18 cw(c5825.3,4408.56) 5825.3,4425 ; 5825.3,4425 cw(c5825.3,4441.44) 5813.67,4429.82 ccw(c5825.3,4441.44) 5825.3,4425 ; 5952.5,4239.21 ccw(c5976.64,4239.21) 5959.57,4222.14 cw(c5976.64,4239.21) 5952.5,4239.21 ; 5952.5,4239.21 cw(c5928.36,4239.21) 5945.43,4222.14 ccw(c5928.36,4239.21) 5952.5,4239.21
GND: BAT.2 BOOT.5 BOOT.6 C1.2 C2.2 C3.1 C4.1 C5.2 C6.2 C7.1 C8.1 C9.1 C10.1 C11.1 C12.1 C13.1 C14.1 C15.1 C16.1 C17.1 C18.1 C19.2 C20.1 C21.1 C22.1 C23.1 C24.1 C25.1 C26.1 DS3.2 JTAG.4 JTAG.6 JTAG.8 JTAG.10 JTAG.12 JTAG.14 JTAG.16 JTAG.18 JTAG.20 KEY1.1 KEY2.1 P1.57 P1.58 P2.59 P2.60 P4.2 P5.2 P6.1 P7.2 R10.1 RESET.2 U1.1 U2.1 U3.2 U4.16 U4.30 U4.31 U4.38 U4.51 U4.61 U4.71 U4.83 U4.94 U4.107 U4.120 U4.130 U4.143 USB_1.5 VCC1.2 VCC1.4 VCC1.6 VCC2.2 VCC2.4 VCC2.6 | length 7526.2
  Top Layer w10: R10.1@4172,4945 4172,4897 4213,4856 4421,4856 JTAG.8@4470,4905 ; 4436.9,4878.5 cw(c4477.66,4867.57) JTAG.8@4469.2,4908.92 ; 4443.5,4871.9 ccw(c4432.57,4912.66) JTAG.8@4473.92,4904.2 ; U4.107@5422.78,5870.03 v1(5477.81,5815) v1@5480,5815 ; v1(5495,4575) U2.1@5572.64,4575 ; U4.120@5561.97,5563.8 5563.8,5563.8 v1(5625,5625) ; U4.94@5603.73,6050.98 5604.02,6050.98 v1(5660,5995) ; C24.1@5650,4927 v1(5650,4985) ; U4.130@5701.17,5424.6 5701.17,5426.17 v1(5760,5485) ; U4.83@5756.85,6204.09 5756.85,6203.15 v1(5815,6145) ; U4.143@5882.12,5243.65 5905.84,5267.37 v1(5905.84,5319.16) ; v1(5989,6244) 5989,6269.21 U4.71@6049.15,6329.37 ; v1(6120,6125) 6123.18,6125 U4.61@6188.35,6190.17 ; v1(6187.55,5495) U4.16@6244.03,5438.52 ; v1(6242,5954.56) 6236.56,5960 U4.51@6327.54,6050.98 ; v4(6330,5660) 6379,5660 ; v2@6392.22,5699.22 cw(c6375.32,5699.22) 6387.27,5687.27 cw(c6399.22,5675.32) v2@6399.22,5692.22 ; U4.30@6438.9,5633.4 6412.29,5660 ; U4.31@6452.82,5647.31 6451.12,5647.31 v2(6399.22,5699.22) 6379,5679 6379,5660 ; v1(6455,5816.53) U4.38@6508.49,5870.03 ; 4172,4920.86 ccw(c4147.86,4920.86) 4164.93,4937.93 cw(c4147.86,4920.86) 4172,4920.86 ; 4172,4920.86 cw(c4196.14,4920.86) 4179.07,4937.93 ccw(c4196.14,4920.86) 4172,4920.86 ; 4425.62,4860.62 ccw(c4381.23,4905) 4444,4905 cw(c4381.23,4905) 4425.62,4860.62 ; 4425.62,4860.62 cw(c4470,4816.23) 4470,4879 ccw(c4470,4816.23) 4425.62,4860.62 ; 4442.69,4877.69 ccw(c4415.37,4905) 4454,4905 cw(c4415.37,4905) 4442.69,4877.69 ; 4442.69,4877.69 cw(c4470,4850.37) 4470,4889 ccw(c4470,4850.37) 4442.69,4877.69 ; 5465.86,5826.95 ccw(c5477.81,5838.9) 5477.81,5822 cw(c5477.81,5838.9) 5465.86,5826.95 ; 5465.86,5826.95 cw(c5453.91,5815) 5470.81,5815 ccw(c5453.91,5815) 5465.86,5826.95 ; 5511.9,4575 ccw(c5511.9,4558.1) 5499.95,4570.05 cw(c5511.9,4558.1) 5511.9,4575 ; 5511.9,4575 cw(c5511.9,4591.9) 5499.95,4579.95 ccw(c5511.9,4591.9) 5511.9,4575 ; 5524.7,4575 ccw(c5524.7,4591.44) 5536.33,4579.82 cw(c5524.7,4591.44) 5524.7,4575 ; 5524.7,4575 cw(c5524.7,4558.56) 5536.33,4570.18 ccw(c5524.7,4558.56) 5524.7,4575 ; 5613.05,5613.05 ccw(c5601.1,5625) 5618,5625 cw(c5601.1,5625) 5613.05,5613.05 ; 5613.05,5613.05 cw(c5625,5601.1) 5625,5618 ccw(c5625,5601.1) 5613.05,5613.05 ; 5648.05,6006.95 ccw(c5660,6018.9) 5660,6002 cw(c5660,6018.9) 5648.05,6006.95 ; 5648.05,6006.95 cw(c5636.1,5995) 5653,5995 ccw(c5636.1,5995) 5648.05,6006.95 ; 5650,4951.14 ccw(c5674.14,4951.14) 5657.07,4934.07 cw(c5674.14,4951.14) 5650,4951.14 ; 5650,4951.14 cw(c5625.86,4951.14) 5642.93,4934.07 ccw(c5625.86,4951.14) 5650,4951.14 ; 5650,4968.1 ccw(c5633.1,4968.1) 5645.05,4980.05 cw(c5633.1,4968.1) 5650,4968.1 ; 5650,4968.1 cw(c5666.9,4968.1) 5654.95,4980.05 ccw(c5666.9,4968.1) 5650,4968.1 ; 5748.05,5473.05 ccw(c5736.1,5485) 5753,5485 cw(c5736.1,5485) 5748.05,5473.05 ; 5748.05,5473.05 cw(c5760,5461.1) 5760,5478 ccw(c5760,5461.1) 5748.05,5473.05 ; 5803.05,6156.95 ccw(c5815,6168.9) 5815,6152 cw(c5815,6168.9) 5803.05,6156.95 ; 5803.05,6156.95 cw(c5791.1,6145) 5808,6145 ccw(c5791.1,6145) 5803.05,6156.95 ; 5905.84,5302.26 ccw(c5888.94,5302.26) 5900.89,5314.21 cw(c5888.94,5302.26) 5905.84,5302.26 ; 5905.84,5302.26 cw(c5922.74,5302.26) 5910.79,5314.21 ccw(c5922.74,5302.26) 5905.84,5302.26 ; 5989,6260.9 ccw(c6005.9,6260.9) 5993.95,6248.95 cw(c6005.9,6260.9) 5989,6260.9 ; 5989,6260.9 cw(c5972.1,6260.9) 5984.05,6248.95 ccw(c5972.1,6260.9) 5989,6260.9 ; 6199.5,5483.05 ccw(c6187.55,5471.1) 6187.55,5488 cw(c6187.55,5471.1) 6199.5,5483.05 ; 6199.5,5483.05 cw(c6211.45,5495) 6194.55,5495 ccw(c6211.45,5495) 6199.5,5483.05 ; 6354.14,5660 ccw(c6354.14,5635.86) 6337.07,5652.93 cw(c6354.14,5635.86) 6354.14,5660 ; 6354.14,5660 cw(c6354.14,5684.14) 6337.07,5667.07 ccw(c6354.14,5684.14) 6354.14,5660 ; 6379,5660 6412.29,5660 ; v2@6399.22,5692.22 cw(c6399.22,5675.32) 6411.17,5687.27 ; v2@6399.22,5692.22 cw(c6399.22,5675.32) 6411.17,5687.27 ; 6411.17,5687.27 cw(c6423.12,5699.22) 6406.22,5699.22 ccw(c6423.12,5699.22) 6411.17,5687.27 ; 6412.29,5660 cw(c6412.29,5654.53) 6417.76,5654.8 ccw(c6412.29,5654.53) 6412.29,5660 ; 6466.95,5828.48 ccw(c6478.9,5816.53) 6462,5816.53 cw(c6478.9,5816.53) 6466.95,5828.48 ; 6466.95,5828.48 cw(c6455,5840.43) 6455,5823.53 ccw(c6455,5840.43) 6466.95,5828.48 ; U4.143@5903.69,5264.87 ccw(c5898.49,5270.06) 5905.84,5270.06 cw(c5898.49,5270.06) U4.143@5903.69,5264.87 ; v1@6120,6132 ccw(c6120,6156.57) 6137.37,6139.2 cw(c6120,6156.57) v1@6120,6132 ; v1@6239,5954.56 cw(c6258,5954.56) 6244.57,5968 ccw(c6258,5954.56) v1@6239,5954.56 ; v1@6249,5954.56 cw(c6292.15,5954.56) 6261.64,5985.07 ccw(c6292.15,5954.56) v1@6249,5954.56 ; 6405.52,5660 cw(c6405.52,5642.8) 6417.68,5654.96 ccw(c6405.52,5642.8) 6405.52,5660
  Top Layer w30: USB_1.5@4321.06,3596.01 4362.85,3596.01 4401,3557.86 4401,3515 v1(4453,3463) ; v1(5185,4310) 5263,4310 C7.1@5268,4315 ; C8.1@5337,4065 C9.1@5453,4065 v1(5453,4163) ; DS3.2@5623.98,3422 DS3.2@5609.94,3407.96 5616.9,3401 5715,3401 5753,3439 ; C2.2@5813.76,3994 5812.76,3995 5735,3995 5714,3974 v1(5714,3891) 5714,3871 ; U1.1@5817.1,3439 5753,3439 ; C23.1@5823,4785 5823,4752 5850,4725 v1(5892,4725) 5953,4725 5988,4760 C22.1@5988,4780 ; U1.1@5825.03,3446.94 5825.03,3350.97 5853,3323 C3.1@5894,3323 C3.1@5897,3323 ; C4.1@5901,3799 5899,3797 5788,3797 5714,3871 ; C6.2@6012.5,4489.94 C5.2@6012.5,4574.94 v1(6140.06,4574.94) ; C20.1@6295.91,4679.09 6295.91,4865.91 v1(6315,4885) ; C1.2@6297,3587.24 6297,3695 6387,3785 BOOT.5@6545,3785 ; C21.1@6524.09,4445.91 6580,4390 v1(6650,4390) ; C18.1@6952,3310 7015,3373 U3.2@7015,3440 ; 5714,3871 cw(c5726.41,3883.41) 5711.44,3892.57 ccw(c5726.41,3883.41) 5714,3871 ; 5753,3439 ccw(c5753,3419.97) 5734.01,3421.19 cw(c5753,3419.97) 5753,3439 ; 5825.03,3362.19 ccw(c5782.78,3362.19) 5812.66,3392.06 cw(c5782.78,3362.19) 5825.03,3362.19 ; 5825.03,3362.19 cw(c5867.28,3362.19) 5837.41,3392.06 ccw(c5867.28,3362.19) 5825.03,3362.19 ; C22.1@5988,4780 cw(c5939.72,4780) 5973.86,4745.86 ccw(c5939.72,4780) C22.1@5988,4780 ; 6297,3655.77 ccw(c6332.07,3655.77) 6307.27,3630.97 cw(c6332.07,3655.77) 6297,3655.77 ; 6297,3655.77 cw(c6261.93,3655.77) 6286.73,3630.97 ccw(c6261.93,3655.77) 6297,3655.77 ; 6509.93,3785 ccw(c6509.93,3820.07) 6534.73,3795.27 cw(c6509.93,3820.07) 6509.93,3785 ; 6509.93,3785 cw(c6509.93,3749.93) 6534.73,3774.73 ccw(c6509.93,3749.93) 6509.93,3785 ; DS3.2@5617.01,3412.47 ccw(c5644.7,3440.17) 5644.7,3401 cw(c5644.7,3440.17) DS3.2@5617.01,3412.47 ; v1@5711,3891 ccw(c5752.04,3891) 5723.02,3861.98 cw(c5752.04,3891) v1@5711,3891 ; v1@5734.88,3423.12 cw(c5773.21,3384.79) 5773.21,3439 ccw(c5773.21,3384.79) v1@5734.88,3423.12 ; 5742.81,3995 cw(c5742.81,3956.51) 5770.03,3983.73 ccw(c5742.81,3956.51) 5742.81,3995 ; 5747.64,3995 ccw(c5747.64,4026.66) 5770.03,4004.27 cw(c5747.64,4026.66) 5747.64,3995 ; 5763.62,3439 ccw(c5763.62,3508.34) 5812.66,3459.31 cw(c5763.62,3508.34) 5763.62,3439 ; 6295.91,4846.15 cw(c6353.85,4846.15) 6312.88,4887.12 ccw(c6353.85,4846.15) 6295.91,4846.15 ; 6295.91,4858 cw(c6329.6,4858) 6313.57,4887.64 ccw(c6329.6,4858) 6295.91,4858
  Bottom Layer w30: v4(6330,5660) 6458,5532 C25.1@6547,5532 C26.1@6635,5532
  other v1: 5737,3421
IIC_SCL: P1.7 P4.3 U4.69 | length 2579.1
  Top Layer w10: U4.69@6076.99,6301.53 6510.47,6735 P1.7@6930,6735 6953.33,6735 6994.36,6776.03 ; P1.7@6918.62,6745.49 cw(c6950.63,6715.98) 6948.86,6759.48 ; P1.7@6925.98,6738.71 cw(c6975.74,6692.84) 6972.99,6760.46 ; 7199.48,6557.35 ccw(c7236.61,6567.3) P4.3@7228.9,6529.64 ; 7207.65,6565.52 cw(c7197.7,6528.39) P4.3@7235.36,6536.1 ; P4.3@7230,6535 7155,6610 7155,6695 7073.97,6776.03 6994.36,6776.03 ; 6870.79,6735 ccw(c6870.79,6794.21) 6912.66,6752.34 cw(c6870.79,6794.21) 6870.79,6735 ; 6870.79,6735 cw(c6870.79,6675.79) 6912.66,6717.66 ccw(c6870.79,6675.79) 6870.79,6735 ; 6894.93,6735 ccw(c6894.93,6770.07) 6919.73,6745.27 cw(c6894.93,6770.07) 6894.93,6735 ; 6894.93,6735 cw(c6894.93,6699.93) 6919.73,6724.73 ccw(c6894.93,6699.93) 6894.93,6735 ; 6994.36,6776.03 cw(c6949.34,6821.04) 6935.38,6758.93 ccw(c6949.34,6821.04) 6994.36,6776.03 ; 7188.13,6576.87 ccw(c7230,6618.74) 7230,6559.53 cw(c7230,6618.74) 7188.13,6576.87 ; 7188.13,6576.87 cw(c7146.26,6535) 7205.47,6535 ccw(c7146.26,6535) 7188.13,6576.87 ; 7205.2,6559.8 ccw(c7230,6584.6) 7230,6549.53 cw(c7230,6584.6) 7205.2,6559.8 ; 7205.2,6559.8 cw(c7180.4,6535) 7215.47,6535 ccw(c7180.4,6535) 7205.2,6559.8 ; P1.7@6930.99,6739.42 ccw(c6939.91,6779.1) 6968.67,6750.34 cw(c6939.91,6779.1) P1.7@6930.99,6739.42 ; P1.7@6933.19,6749.17 ccw(c6944.63,6800.07) 6981.52,6763.18 cw(c6944.63,6800.07) P1.7@6933.19,6749.17
IIC_SDL: P1.6 P4.4 U4.70 | length 2531.9
  Top Layer w10: U4.70@6063.07,6315.45 6523.65,6776.03 6951.03,6776.03 7010,6835 P1.6@7030,6835 7040,6825 7070,6825 ; 6977.89,6796.51 ccw(c6958.74,6867.98) P1.6@7025.89,6836.9 ; 6998.53,6802.04 ccw(c6983.99,6856.29) P1.6@7034.97,6832.7 ; 7000.52,6812.57 ccw(c6991.1,6847.74) P1.6@7025.7,6836.41 ; 7199.48,6657.35 ccw(c7236.61,6667.3) P4.4@7228.9,6629.64 ; 7207.65,6665.52 cw(c7197.7,6628.39) P4.4@7235.36,6636.1 ; P4.4@7230,6635 7180,6685 7180,6715 7070,6825 ; 7070,6825 cw(c7070,6840.91) 7054.26,6838.58 ccw(c7070,6840.91) 7070,6825 ; 7188.13,6676.87 ccw(c7230,6718.74) 7230,6659.53 cw(c7230,6718.74) 7188.13,6676.87 ; 7188.13,6676.87 cw(c7146.26,6635) 7205.47,6635 ccw(c7146.26,6635) 7188.13,6676.87 ; 7205.2,6659.8 ccw(c7230,6684.6) 7230,6649.53 cw(c7230,6684.6) 7205.2,6659.8 ; 7205.2,6659.8 cw(c7180.4,6635) 7215.47,6635 ccw(c7180.4,6635) 7205.2,6659.8 ; 6953.99,6778.99 cw(c7030,6702.97) 7030,6810.47 ccw(c7030,6702.97) 6953.99,6778.99 ; 6971.06,6796.06 cw(c7030,6737.12) 7030,6820.47 ccw(c7030,6737.12) 6971.06,6796.06 ; 6988.13,6813.13 cw(c7030,6771.26) 7030,6830.47 ccw(c7030,6771.26) 6988.13,6813.13 ; P1.6@7044.37,6837.12 ccw(c7058.41,6839.19) 7058.41,6825 cw(c7058.41,6839.19) P1.6@7044.37,6837.12 ; P1.6@7047.34,6817.66 cw(c7065.07,6799.93) 7065.07,6825 ccw(c7065.07,6799.93) P1.6@7047.34,6817.66
IIC_XCL: P4.6
IIC_XDL: P4.5
INT: P4.8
